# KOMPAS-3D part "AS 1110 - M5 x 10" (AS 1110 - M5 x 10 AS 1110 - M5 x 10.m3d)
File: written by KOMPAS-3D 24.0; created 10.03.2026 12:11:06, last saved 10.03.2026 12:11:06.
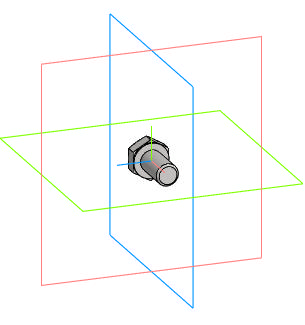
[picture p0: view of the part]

Document properties: Автор: R2D2; Полное имя файла: E:\Работа\Зайцев\BV3232P(4pc)-FP-3WL-F-ISO-H Кран шаровой DN.ru Ду15-100 Ру16\DN25\исходные материалы\AS 1110 - M5 x 10 AS 1110 - M5 x 10.m3d

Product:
- Body: Solid1  | qty 1
- Part/product: AS 1110 - M5 x 10
    Комментарий: Болты и винты   шестигранные точные   метрические ISO
    additional columns: Сталь, мягкая

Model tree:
1. Solid1  (labels: Solid1)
